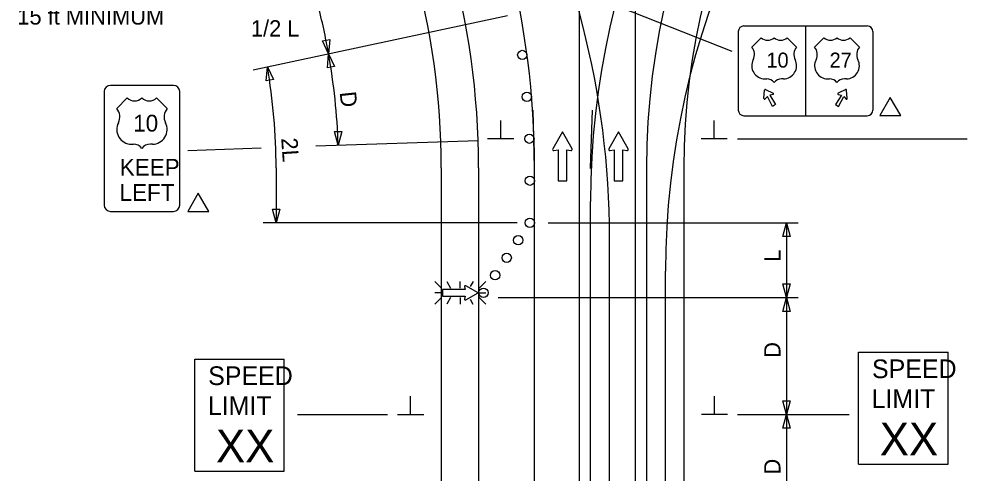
# Model space of a CAD drawing. Extents: x 16729 to 18464, y 5737 to 6974.
# Drawn here: x 16740.5 to 17147.3, y 6438.7 to 6633.2 of the extents above; entities that cross this region are included whole.
import ezdxf

# ---------------------------------------------------------------- set-up
doc = ezdxf.new("R2010")
doc.units = 0
for name, color, linetype in [('ALI_LEGAL_EX', 7, 'Continuous'), ('MT_SCRATCH_LEVEL_E', 7, 'Continuous'), ('PAVT_EDGE_EX', 7, 'Continuous'), ('TRAFFIC_SIGNS_PR', 7, 'Continuous'), ('TYPICAL_EX', 7, 'Continuous'), ('TYPICAL_TEXT_DIMEN_PR', 7, 'Continuous')]:
    doc.layers.add(name, color=color, linetype=linetype)

msp = doc.modelspace()

# ---------------------------------------------------------------- linework, layer by layer
at = {"layer": 'ALI_LEGAL_EX'}
for p, q in [((16980.68, 6974.12), (16980.68, 6155.98)), ((17004.68, 6974.12), (17004.68, 6155.98)), ((16980.68, 6891.53), (16980.68, 6027.61)), ((17004.68, 6891.53), (17004.68, 6027.61)), ((16961.51, 6069.17), (16961.51, 6569.52)), ((16985.51, 6054.68), (16985.51, 6555.03)), ((16993.65, 6039.29), (16993.65, 6539.64)), ((17017.65, 6024.8), (17017.65, 6525.15))]:
    msp.add_line(p, q, dxfattribs=at)
for points in [[(16961.46, 6569.17), (16961.51, 6569.52), (16960.94, 6594.16)], [(16985.56, 6569.17), (16985.51, 6569.52), (16986.34, 6594.15)], [(16961.51, 6469.17), (16961.51, 6494.17)], [(16985.51, 6469.17), (16985.51, 6494.17)]]:
    msp.add_lwpolyline(points, dxfattribs=at)
for centre, radius, start, end in [((16597.51, 6569.52), 364, 0, 57.2958), ((16629.65, 6539.64), 364, 0, 57.2958), ((17325.51, 6555.03), 340, 129.5666, 180), ((17357.65, 6525.15), 340, 129.5666, 180)]:
    msp.add_arc(centre, radius, start, end, dxfattribs=at)
at = {"layer": 'MT_SCRATCH_LEVEL_E'}
for p, q in [((16973.43, 6584.82), (16969.32, 6577.59)), ((16977.58, 6577.59), (16973.43, 6584.82)), ((16997.48, 6584.82), (16993.37, 6577.59)), ((17001.63, 6577.59), (16997.48, 6584.82)), ((16969.8, 6576.9), (16971.58, 6577.22)), ((16971.58, 6577.22), (16971.58, 6563.96)), ((16975.32, 6563.96), (16975.32, 6577.22)), ((16975.32, 6577.22), (16977.1, 6576.9)), ((16993.85, 6576.9), (16995.63, 6577.22)), ((16995.63, 6577.22), (16995.63, 6563.96)), ((16999.37, 6563.96), (16999.37, 6577.22)), ((16999.37, 6577.22), (17001.15, 6576.9)), ((16971.58, 6563.96), (16975.32, 6563.96)), ((16995.63, 6563.96), (16999.37, 6563.96))]:
    msp.add_line(p, q, dxfattribs=at)
for centre, start, end in [((16969.73, 6577.36), 150.4248, 279.9638), ((16977.17, 6577.36), 260.0362, 29.7731), ((16993.78, 6577.36), 150.4248, 279.9638), ((17001.22, 6577.36), 260.0362, 29.7731)]:
    msp.add_arc(centre, 0.463, start, end, dxfattribs=at)
at = {"layer": 'PAVT_EDGE_EX'}
for p, q in [((16921.51, 6569.52), (16921.51, 6043.9)), ((16937.51, 6569.52), (16937.51, 6043.9)), ((17009.51, 6569.52), (17009.51, 6043.9)), ((17025.51, 6569.52), (17025.51, 6043.9))]:
    msp.add_line(p, q, dxfattribs=at)
for centre, radius, start, end in [((16597.51, 6569.52), 340, 0, 62.1564), ((16597.51, 6569.52), 324, 0, 62.1564), ((17325.51, 6569.52), 316, 123.7854, 180), ((17325.51, 6569.52), 300, 123.7854, 180), ((17325.51, 6569.52), 300, 180, 180.00000277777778)]:
    msp.add_arc(centre, radius, start, end, dxfattribs=at)
at = {"layer": 'TRAFFIC_SIGNS_PR'}
for p, q in [((17048.86, 6627.84), (17048.86, 6594.19)), ((17051.26, 6630.24), (17104.13, 6630.24)), ((17077.7, 6630.24), (17077.7, 6591.79)), ((17106.53, 6627.84), (17106.53, 6594.19)), ((16806.71, 6604.81), (16779.71, 6604.81)), ((16777.01, 6602.11), (16777.01, 6553.51)), ((16809.41, 6553.51), (16809.41, 6602.11)), ((17059.85, 6599.15), (17060.14, 6602.78)), ((17060.51, 6602.99), (17063.79, 6601.42)), ((17094.88, 6602.99), (17091.6, 6601.42)), ((17095.54, 6599.15), (17095.25, 6602.78)), ((17051.26, 6591.79), (17104.13, 6591.79)), ((16779.71, 6550.81), (16806.71, 6550.81)), ((16921.58, 6517.92), (16918.76, 6520.74)), ((16923.88, 6520.74), (16925.51, 6517.92)), ((16929.67, 6517.92), (16929.67, 6520.74)), ((16935.13, 6520.74), (16933.93, 6518.65)), ((16940.57, 6520.74), (16937.75, 6517.92)), ((16921.58, 6515.89), (16918.76, 6515.89)), ((16921.58, 6513.86), (16918.76, 6511.04)), ((16925.53, 6513.86), (16923.9, 6511.04)), ((16929.67, 6513.86), (16929.67, 6511.04)), ((16937.75, 6515.89), (16940.57, 6515.89)), ((16940.57, 6511.04), (16937.75, 6513.86)), ((16933.85, 6513.23), (16935.11, 6511.04)), ((17100.39, 6490.51), (17138.79, 6490.51)), ((17100.39, 6442.51), (17100.39, 6490.51)), ((17138.79, 6442.51), (17138.79, 6490.51)), ((16815.83, 6487.55), (16854.23, 6487.55)), ((16815.83, 6439.55), (16815.83, 6487.55)), ((16854.23, 6439.55), (16854.23, 6487.55)), ((17100.39, 6442.51), (17138.79, 6442.51)), ((16815.83, 6439.55), (16854.23, 6439.55))]:
    msp.add_line(p, q, dxfattribs=at)
for points in [[(17063.75, 6600.94), (17062.34, 6600.55), (17064.86, 6596.56), (17063.53, 6595.8), (17061.33, 6599.97), (17060.29, 6598.94)], [(17091.64, 6600.94), (17093.05, 6600.55), (17090.53, 6596.56), (17091.86, 6595.8), (17094.06, 6599.97), (17095.1, 6598.94)], [(16931.49, 6518.57), (16931.72, 6517.28), (16922, 6517.28), (16922, 6514.53), (16931.72, 6514.53), (16931.49, 6513.23)], [(16931.99, 6512.88), (16937.3, 6515.89), (16931.99, 6518.93)]]:
    msp.add_lwpolyline(points, dxfattribs=at)
for centre in [(16956.26, 6617.81), (16958.22, 6599.92), (16959.28, 6581.96), (16959.5, 6563.96), (16959.5, 6545.96), (16959.5, 6545.96), (16954.53, 6538.45), (16949.56, 6530.94), (16944.59, 6523.44), (16939.62, 6515.93)]:
    msp.add_circle(centre, 2, dxfattribs=at)
for centre, radius, start, end in [((17051.26, 6627.84), 2.4, 90, 180), ((17051.26, 6627.84), 2.4, 90, 180), ((17104.13, 6627.84), 2.4, 0, 90), ((16779.71, 6602.1), 2.7, 90, 180), ((16806.71, 6602.1), 2.7, 0, 90), ((17060.4, 6602.76), 0.261, 64.4823, 175.5177), ((17094.99, 6602.76), 0.261, 4.4823, 115.5177), ((17060.11, 6599.13), 0.261, 175.5177, 314.0115), ((17063.68, 6601.19), 0.261, 285.9885, 64.4823), ((17091.71, 6601.19), 0.261, 115.5177, 254.0115), ((17095.28, 6599.13), 0.261, 225.9885, 4.4823), ((17051.26, 6594.19), 2.4, 180, 270), ((17104.13, 6594.19), 2.4, 270, 0), ((16779.71, 6553.5), 2.7, 180, 270), ((16806.71, 6553.5), 2.7, 270, 0), ((16931.83, 6518.63), 0.341, 61.4833, 189.9593), ((16931.83, 6513.18), 0.341, 170.7308, 298.8916)]:
    msp.add_arc(centre, radius, start, end, dxfattribs=at)
at = {"layer": 'TYPICAL_EX'}
for p, q in [((17054.62, 6621.23), (17058.62, 6625.23)), ((17073.84, 6621.23), (17069.84, 6625.23)), ((17081.55, 6621.23), (17085.55, 6625.23)), ((17100.77, 6621.23), (17096.77, 6625.23)), ((17060.22, 6607.6), (17061.02, 6607.6)), ((17068.24, 6607.6), (17067.44, 6607.6)), ((17087.15, 6607.6), (17087.95, 6607.6)), ((17095.17, 6607.6), (17094.37, 6607.6)), ((16782.41, 6594.91), (16786.91, 6599.41)), ((16804.01, 6594.91), (16799.51, 6599.41)), ((16788.7, 6579.59), (16789.6, 6579.59)), ((16797.71, 6579.59), (16796.81, 6579.59))]:
    msp.add_line(p, q, dxfattribs=at)
for centre, radius, start, end in [((17061.43, 6628.15), 4.05, 226.1404, 313.8596), ((17067.03, 6628.15), 4.05, 226.1404, 313.8596), ((17088.36, 6628.15), 4.05, 226.1404, 313.8596), ((17093.96, 6628.15), 4.05, 226.1404, 313.8596), ((17050.82, 6618.02), 4.97, 333.0977, 40.1936), ((17077.64, 6618.02), 4.97, 139.8064, 206.9023), ((17077.75, 6618.02), 4.97, 333.0977, 40.1936), ((17104.57, 6618.02), 4.97, 139.8064, 206.9023), ((17060.23, 6613.2), 5.6, 152.6698, 269.9013), ((17068.23, 6613.2), 5.6, 270.0987, 27.3302), ((17087.16, 6613.2), 5.6, 152.6698, 269.9013), ((17095.16, 6613.2), 5.6, 270.0987, 27.3302), ((17061.03, 6603.59), 4.01, 37.1038, 90.1385), ((17067.43, 6603.59), 4.01, 89.8615, 142.8962), ((17087.96, 6603.59), 4.01, 37.1038, 90.1385), ((17094.36, 6603.59), 4.01, 89.8615, 142.8962), ((16790.06, 6602.68), 4.55, 226.1404, 313.8596), ((16796.36, 6602.68), 4.55, 226.1404, 313.8596), ((16778.14, 6591.3), 5.58, 333.0977, 40.1936), ((16808.27, 6591.3), 5.58, 139.8064, 206.9023), ((16788.71, 6585.89), 6.29, 152.6698, 269.9013), ((16797.7, 6585.89), 6.29, 270.0987, 27.3302), ((16789.61, 6575.09), 4.51, 37.1038, 90.1385), ((16796.8, 6575.09), 4.51, 89.8615, 142.8962)]:
    msp.add_arc(centre, radius, start, end, dxfattribs=at)
at = {"layer": 'TYPICAL_TEXT_DIMEN_PR'}
for p, q in [((16964.45, 6651.69), (17046.11, 6619.48)), ((16840.84, 6611.45), (16949.94, 6634.73)), ((16870.65, 6623.86), (16872.19, 6624.13)), ((16873.22, 6618.36), (16870.65, 6623.86)), ((16872.19, 6624.13), (16873.74, 6624.4)), ((16873.74, 6624.4), (16873.22, 6618.36)), ((16872.69, 6612.31), (16873.22, 6618.36)), ((16873.22, 6618.36), (16875.79, 6612.86)), ((16846.44, 6606.71), (16846.97, 6612.76)), ((16846.97, 6612.76), (16849.54, 6607.26)), ((16874.24, 6612.59), (16872.69, 6612.31)), ((16875.79, 6612.86), (16874.24, 6612.59)), ((16849.54, 6607.26), (16847.99, 6606.98)), ((16847.99, 6606.98), (16846.44, 6606.71)), ((16946.99, 6581.91), (16946.99, 6589.7)), ((17038.53, 6581.91), (17038.53, 6589.7)), ((16877.34, 6579.16), (16875.77, 6585.02)), ((16875.77, 6585.02), (16877.34, 6585.02)), ((16877.34, 6585.02), (16878.91, 6585.02)), ((16878.91, 6585.02), (16877.34, 6579.16)), ((16867.78, 6578.83), (16937.31, 6581.22)), ((16952.61, 6581.91), (16941.36, 6581.91)), ((17044.15, 6581.91), (17032.9, 6581.91)), ((17048.51, 6581.91), (17146.98, 6581.91)), ((16812.87, 6576.94), (16844.31, 6578.02)), ((16850.69, 6569.52), (16850.69, 6545.96)), ((16850.69, 6545.96), (16849.12, 6551.82)), ((16849.12, 6551.82), (16850.69, 6551.82)), ((16850.69, 6551.82), (16852.26, 6551.82)), ((16852.26, 6551.82), (16850.69, 6545.96)), ((16954.01, 6545.96), (16845.14, 6545.96)), ((16967.28, 6545.96), (17074.51, 6545.96)), ((17067.94, 6540.1), (17069.51, 6545.96)), ((17069.51, 6545.96), (17069.51, 6513.85)), ((17069.51, 6545.96), (17071.08, 6540.1)), ((17069.51, 6540.1), (17067.94, 6540.1)), ((17071.08, 6540.1), (17069.51, 6540.1)), ((17069.51, 6513.85), (17067.94, 6519.72)), ((17067.94, 6519.72), (17069.51, 6519.72)), ((17069.51, 6519.72), (17071.08, 6519.72)), ((17071.08, 6519.72), (17069.51, 6513.85)), ((16945.91, 6513.85), (17074.51, 6513.85)), ((17067.94, 6507.99), (17069.51, 6513.85)), ((17069.51, 6513.85), (17069.51, 6463.85)), ((17069.51, 6513.85), (17071.08, 6507.99)), ((17069.51, 6507.99), (17067.94, 6507.99)), ((17071.08, 6507.99), (17069.51, 6507.99)), ((16908.39, 6463.85), (16908.39, 6471.64)), ((17038.64, 6463.85), (17038.64, 6471.64)), ((17069.51, 6463.85), (17067.94, 6469.72)), ((17067.94, 6469.72), (17069.51, 6469.72)), ((17069.51, 6469.72), (17071.08, 6469.72)), ((17071.08, 6469.72), (17069.51, 6463.85)), ((16859.95, 6463.85), (16898.51, 6463.85)), ((16902.76, 6463.85), (16914.01, 6463.85)), ((17044.26, 6463.85), (17033.01, 6463.85)), ((17048.51, 6463.85), (17096.34, 6463.85)), ((17067.94, 6457.99), (17069.51, 6463.85)), ((17069.51, 6463.85), (17069.51, 6413.85)), ((17069.51, 6463.85), (17071.08, 6457.99)), ((17069.51, 6457.99), (17067.94, 6457.99)), ((17071.08, 6457.99), (17069.51, 6457.99))]:
    msp.add_line(p, q, dxfattribs=at)
for points in [[(17114.01, 6599.66), (17109.48, 6591.83), (17118.53, 6591.83)], [(16817.37, 6558.64), (16812.84, 6550.81), (16821.89, 6550.81)]]:
    msp.add_lwpolyline(points, close=True, dxfattribs=at)
for radius, start, end in [(280, 10.0461, 14.4629), (280, 1.9734, 10.046), (253.18, 0, 9.834)]:
    msp.add_arc((16597.51, 6569.52), radius, start, end, dxfattribs=at)

# ---------------------------------------------------------------- texts
at = {"layer": 'TRAFFIC_SIGNS_PR'}
for s, height, p in [('10', 6.408, (17060.89, 6612.42)), ('27', 6.408, (17087.99, 6612.42)), ('10', 7.2, (16789.45, 6585.01)), ('KEEP', 7.2, (16783.69, 6566.11)), ('LEFT', 7.2, (16783.59, 6555.31)), ('SPEED', 8, (17106.16, 6479.37)), ('SPEED', 8, (16821.6, 6476.41)), ('LIMIT', 8, (17106, 6466.57)), ('LIMIT', 8, (16821.44, 6463.61)), ('XX', 14.031, (16824.94, 6443.31)), ('XX', 14.031, (17109.5, 6446.27))]:
    msp.add_text(s, height=height, dxfattribs=at).set_placement(p)
at = {"layer": 'TYPICAL_TEXT_DIMEN_PR'}
for s, p in [('15 ft MINIMUM', (16739.78, 6630.83)), ('1/2 L', (16839.91, 6625.71))]:
    msp.add_text(s, height=7, dxfattribs=at).set_placement(p)
for s, rotation, p in [('D', 276.0098, (16877.95, 6601.84)), ('2L', 273.8016, (16852.9, 6582.16)), ('L', 90, (17066.95, 6529.26)), ('D', 90, (17066.95, 6488.07)), ('D', 90, (17066.95, 6438.07))]:
    msp.add_text(s, height=7, rotation=rotation, dxfattribs=at).set_placement(p)

doc.saveas('drawing.dxf')
